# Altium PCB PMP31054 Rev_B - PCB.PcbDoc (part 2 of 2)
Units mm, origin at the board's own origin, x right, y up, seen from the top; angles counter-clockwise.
Board outline 89.28 x 61.72 mm, 4 copper layers (Top Layer, GND, Signal Layer 2, Bottom Layer), stack 2.134 mm thick; 58 components, 20 nets, 96 pads, 56 vias.
Unrouted connection lines stored in the file: 4.
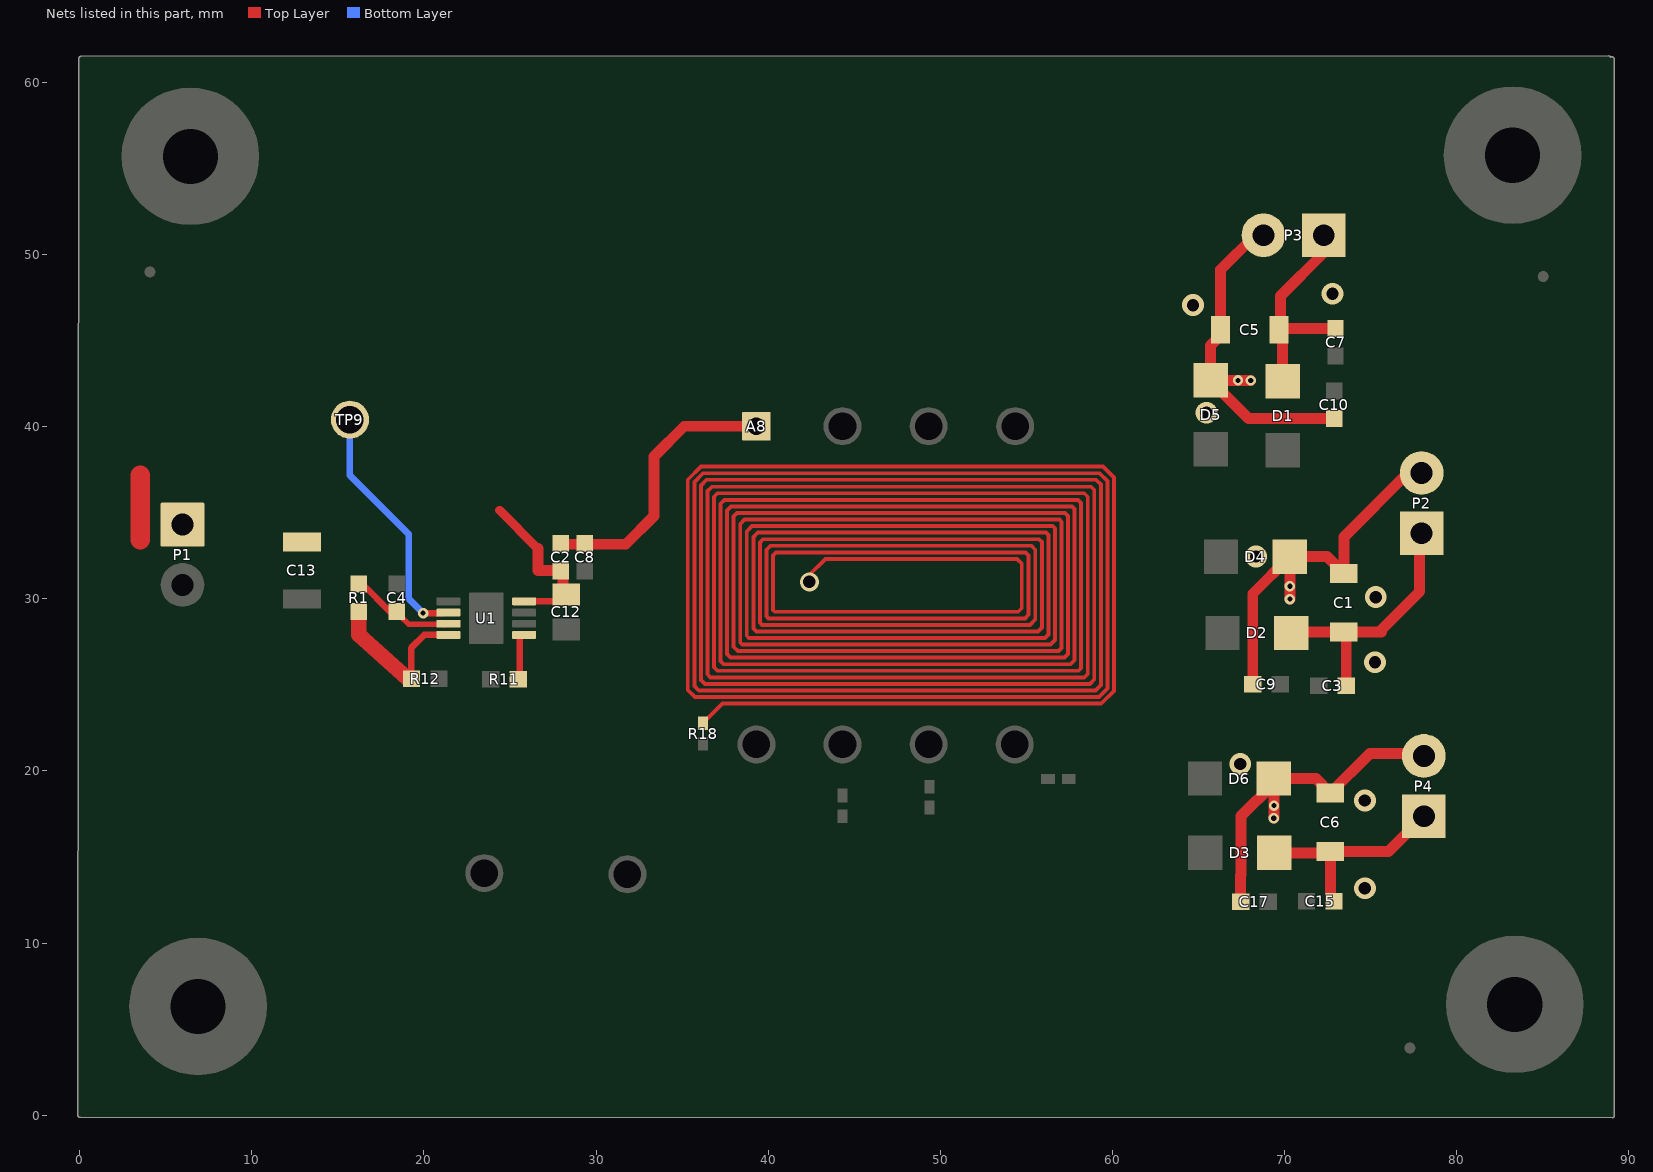
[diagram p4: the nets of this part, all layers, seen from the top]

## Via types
v1: diameter 0.6, hole 0.3, Top Layer to Bottom Layer, 29 vias
v2: diameter 1.27, hole 0.711, Top Layer to Bottom Layer, 23 vias
v3: diameter 1.1, hole 0.71, Top Layer to Bottom Layer, 4 vias

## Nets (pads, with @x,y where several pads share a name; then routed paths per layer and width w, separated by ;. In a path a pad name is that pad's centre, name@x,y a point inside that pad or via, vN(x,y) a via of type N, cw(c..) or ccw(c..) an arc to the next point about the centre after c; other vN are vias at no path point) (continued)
NetA8_1: A8.1 C2.2 C8.1 R18.1 | length 839
  Top Layer w0.225: R18.1@36.22,22.782 37.354,23.915 42.621,23.915 59.36,23.915 60.096,24.652 60.096,37.047 59.461,37.682 36.093,37.682 35.331,36.92 35.331,24.706 35.741,24.296 59.233,24.296 59.715,24.779 59.715,36.844 59.263,37.296 36.216,37.296 35.715,36.796 35.715,24.928 35.966,24.677 59.03,24.677 59.334,24.982 59.334,36.641 59.055,36.92 36.424,36.92 36.093,36.59 36.093,25.287 36.322,25.058 58.699,25.058 58.953,25.312 58.953,36.336 58.776,36.514 36.728,36.514 36.474,36.26 36.474,25.617 36.652,25.439 58.369,25.439 58.572,25.642 58.572,35.929 58.369,36.133 37.059,36.133 36.855,35.929 36.855,26.023 37.059,25.82 58.039,25.82 58.191,25.973 58.191,35.572 58.014,35.75 37.461,35.75 37.236,35.525 37.236,26.379 37.414,26.201 57.582,26.201 57.81,26.43 57.81,35.218 57.658,35.371 37.846,35.371 37.617,35.142 37.617,26.785 37.821,26.582 57.226,26.582 57.429,26.785 57.429,34.812 57.252,34.99 38.202,34.99 37.998,34.786 37.998,27.217 38.252,26.963 56.871,26.963 57.048,27.141 57.048,34.482 56.921,34.609 38.633,34.609 38.379,34.355 38.379,27.471 38.506,27.344 56.413,27.344 56.667,27.598 56.667,34.101 56.54,34.228 39.065,34.228 38.76,33.923 38.76,27.852 38.887,27.725 56.083,27.725 56.286,27.928 56.286,33.707 56.147,33.847 39.395,33.847 39.141,33.593 39.141,28.284 39.319,28.106 55.677,28.106 55.905,28.335 55.905,33.309 55.751,33.464 39.702,33.464 39.522,33.284 39.522,28.614 39.649,28.487 55.22,28.487 55.524,28.792 55.524,32.856 55.296,33.085 40.132,33.085 39.903,32.856 39.903,28.995 40.03,28.868 54.93,28.868 55.138,29.077 55.138,32.526 54.96,32.704 40.462,32.704 40.284,32.526 40.284,29.351 40.386,29.249 54.534,29.249 54.737,29.452 54.737,32.043 54.458,32.323 43.332,32.323 42.393,31.383 v3(42.393,30.988) 42.393,30.683 v3@42.266,30.556
  Top Layer w0.635: C2.2@27.953,33.172 29.35,33.172 31.725,33.172 33.376,34.823 33.376,38.278 35.128,40.03 A8.1@39.319,40.03
NetC1_1: C1.1 C3.1 D2.1 P2.1 | length 15
  Top Layer w0.635: D2.1@70.402,28.016 70.453,28.067 C1.1@73.457,28.067 ; C3.1@73.596,24.943 73.596,27.927 C1.1@73.457,28.067 ; 75.641,28.067 75.514,28.067 ; P2.1@78.054,33.579 77.864,33.389 77.864,30.417 75.514,28.067 ; C1.1@73.457,28.067 75.514,28.067
NetC1_2: C1.2 C9.2 D4.2 P2.2 | length 22.5
  Top Layer w0.635: C9.2@68.161,25.044 68.161,30.292 D4.2@70.319,32.451 ; v1(70.319,29.984) v1(70.319,30.734) D4.2@70.319,32.451 ; P2.2@77.978,37.313 77.168,37.313 73.457,33.602 C1.2@73.457,31.467 72.473,32.451 D4.2@70.319,32.451
  other v2: 75.26,26.314 75.311,30.097 68.351,32.459
NetC2_1: C2.1 C12.1 C13.1 P1.1 U1.8 | length 14.2
  Top Layer w0.381: U1.8@25.822,29.852 25.558,29.852 27.871,29.852 28.143,30.124 C12.1@28.27,30.251
  Top Layer w0.508: 24.397,35.141 26.619,32.918
  Top Layer w0.635: 26.619,32.918 26.619,31.648 28.016,31.648 28.08,31.585 28.08,30.442 C12.1@28.27,30.251
  Top Layer w1.143: 3.505,33.426 3.505,37.173
NetC4_1: C4.1 R1.2 U1.3 | length 6.3
  Top Layer w0.32: C4.1@18.237,29.045 18.593,29.045 19.126,28.512 21.382,28.512 U1.3@21.422,28.552
  Top Layer w0.381: R1.2@16.205,31.077 C4.1@18.237,29.045 ; U1.3@21.158,28.527 U1.3@21.158,28.552
NetC5_1: C5.1 C7.1 D1.1 P3.1 | length 12.9
  Top Layer w0.635: C5.1@69.774,45.695 C5.1@69.774,45.707 ; D1.1@69.901,42.64 69.901,45.439 C5.1@69.696,45.644 69.759,45.707 C5.1@69.774,45.707 ; P3.1@72.288,51.13 72.288,50.114 69.774,47.6 C5.1@69.774,45.707 ; C7.1@72.961,45.72 C7.1@72.974,45.707 C5.1@69.774,45.707
NetC5_2: C5.2 C10.2 D5.2 P3.2 | length 20.4
  Top Layer w0.635: v1(68.047,42.691) 68.04,42.697 v1(67.31,42.697) 65.716,42.697 D5.2@65.71,42.691 ; P3.2@68.783,51.13 68.304,51.13 66.296,49.122 C5.2@66.296,45.644 66.296,45.314 65.71,44.728 D5.2@65.71,42.691 ; C10.2@72.89,40.475 67.926,40.475 D5.2@65.71,42.691
  other v2: 65.481,40.818 64.694,47.066 72.796,47.727
NetC6_1: C6.1 C15.1 D3.1 P4.1 | length 12.6
  Top Layer w0.635: D3.1@69.412,15.24 72.591,15.24 C6.1@72.669,15.318 ; C15.1@72.885,12.421 72.669,12.636 C6.1@72.669,15.318 ; P4.1@78.105,17.367 76.056,15.318 C6.1@72.669,15.318
NetC6_2: C6.2 C17.2 D6.2 P4.2 | length 20
  Top Layer w0.635: C17.2@67.462,12.395 67.462,13.919 67.488,13.945 67.488,17.374 D6.2@69.386,19.272 ; v1(69.386,17.253) D6.2@69.386,19.272 ; P4.2@78.105,21.017 74.968,21.017 C6.2@72.669,18.718 71.829,19.558 D6.2@69.386,19.558 D6.2@69.386,19.272
  other v1: 69.393,17.983
  other v2: 74.676,13.183 74.676,18.288 67.437,20.396
NetR1_1: R1.1 R12.2 U1.4 | length 9
  Top Layer w0.381: R12.2@19.063,25.362 19.253,25.552 19.253,27.14 20.015,27.902 U1.4@21.158,27.902
  Top Layer w0.889: R1.1@16.205,29.045 16.205,27.902 R12.2@19.063,25.362
NetR11_2: R11.2 U1.5 | length 2.8
  Top Layer w0.381: R11.2@25.286,25.298 R11.2@25.413,25.425 ; R11.2@25.558,25.298 U1.5@25.558,27.902
NetTP9_1: TP9.1 U1.2 | length 13.2
  Top Layer w0.381: v1(19.952,29.172) 21.128,29.172 U1.2@21.158,29.202
  Bottom Layer w0.381: TP9.1@15.697,39.395 15.697,37.173 19.126,33.744 19.126,29.997 v1(19.952,29.172)
pads on no net: FID1.1 FID2.1 FID3.1 FID4.1 FID5.1 FID6.1 H1.1 H2.1 H3.1 H4.1 H5.0 H6.0 H7.0 H8.0

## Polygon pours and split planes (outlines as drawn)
GND on Top Layer "TOP_LAYER_GND_P073" (solid, remove dead copper, pour order 73): 1.981,32.492 30.429,32.492 30.429,26.417 32.842,24.409 32.842,7.963 2.997,7.963 1.981,7.963
NetC2_1 on Top Layer "TOP_LAYER_NETC2_1_P094" (solid, remove dead copper, pour order 94): 1.93,41.427 1.93,32.083 4.067,32.083 4.293,31.858 32.537,31.858 32.537,42.126 3.505,42.126
no net on Top Layer "TOP_LAYER_NONET_P067" (solid, remove dead copper, pour order 67): 24.333,35.585 24.397,35.649 26.429,35.649 27.064,35.014 27.104,32.41 27.953,31.648 27.993,30.78 26.767,30.78 26.088,31.013 24.524,31.013 24.333,31.204
NetA6_1 on Top Layer "TOP_LAYER_NETA6_1_P086" (solid, remove dead copper, pour order 86): 54.03,34.468 56.053,34.468 56.09,34.505 56.09,36.035 56.35,36.294 61.28,36.294 61.874,36.889 61.874,39.383 61.401,39.856 54.226,39.856 54.03,39.66
NetA3_1 on Top Layer "TOP_LAYER_NETA3_1_P076" (solid, remove dead copper, pour order 76): 53.162,25.565 55.194,25.565 55.44,24.359 55.639,24.041 59.385,24.041 59.576,23.787 59.576,22.459 59.116,22.136 54.496,22.136 53.204,23.427 53.204,23.914
GND on Bottom Layer "BOTTOM_LAYER_GND_P075" (solid, remove dead copper, pour order 75): 1.88,40.94 3.505,42.189 32.055,42.189 32.055,8.941 32.842,8.153 32.588,7.899 1.88,7.899
NetC6_2 on Bottom Layer "Bottom Layer-NetC6_2" (solid, pour order 202): 63.551,20.041 66.116,22.606 79.604,22.606 80.137,22.073 80.137,15.723 75.133,10.719 64.719,10.719 63.551,11.887
NetC1_2 on Bottom Layer "Bottom Layer-NetC1_2" (solid, pour order 198): 65.075,33.579 66.015,34.519 72.974,34.519 73.05,34.519 75.032,36.474 75.032,37.973 75.057,37.998 76.352,39.294 79.146,39.294 80.086,38.354 80.086,29.439 75.667,25.019 74.219,23.571 66.599,23.571 65.075,25.869
NetC5_2 on Bottom Layer "Bottom Layer-NetC5_2" (solid, pour order 194): 64.11,37.047 63.398,37.758 63.398,50.521 65.634,52.756 70.333,52.756 74.168,48.92 74.168,47.523 74.168,39.155 72.06,37.047
GND on GND "GND-No Net" (solid, pour order 170): 1.88,1.575 1.88,58.191 1.854,58.217 2.21,58.572 41.758,58.572 41.758,1.575
NetC1_2 on GND "GND-NetC1_2" (solid, pour order 184): 65.075,33.579 66.015,34.519 72.974,34.519 73.05,34.519 75.032,36.474 75.032,37.973 75.057,37.998 76.352,39.294 79.146,39.294 80.086,38.354 80.086,29.439 75.667,25.019 74.219,23.571 66.599,23.571 65.075,25.869
NetC6_2 on GND "GND-NetC6_2" (solid, pour order 186): 63.551,20.041 66.116,22.606 79.604,22.606 80.137,22.073 80.137,15.723 75.133,10.719 64.719,10.719 63.551,11.887
NetC5_2 on GND "GND-NetC5_2" (solid, pour order 174): 64.11,37.047 63.398,37.758 63.398,50.521 65.634,52.756 70.333,52.756 74.168,48.92 74.168,47.523 74.168,39.155 72.06,37.047
NetC6_2 on Signal Layer 2 "Signal Layer 2-NetC6_2" (solid, pour order 200): 63.551,20.041 66.116,22.606 79.604,22.606 80.137,22.073 80.137,15.723 75.133,10.719 64.719,10.719 63.551,11.887
NetC1_2 on Signal Layer 2 "Signal Layer 2-NetC1_2" (solid, pour order 196): 65.075,33.579 66.015,34.519 72.974,34.519 73.05,34.519 75.032,36.474 75.032,37.973 75.057,37.998 76.352,39.294 79.146,39.294 80.086,38.354 80.086,29.439 75.667,25.019 74.219,23.571 66.599,23.571 65.075,25.869
NetC5_2 on Signal Layer 2 "Signal Layer 2-NetC5_2" (solid, pour order 190): 64.11,37.047 63.398,37.758 63.398,50.521 65.634,52.756 70.333,52.756 74.168,48.92 74.168,47.523 74.168,39.155 72.06,37.047

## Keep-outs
Keep-Out Layer:
  text ".Layer_Name" at -57.531,-19.24 h1.52

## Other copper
Top Layer:
  text ".Layer_Name" at -57.531,-19.24 h1.52
GND:
  pour cut-out: 41.783,42.075 41.745,42.113 35.56,42.113 33.02,39.573 33.02,21.666 35.865,18.821 41.808,18.821
  pour cut-out: 38.361,34.341 38.361,27.457 39.086,26.732 56.979,26.732 56.979,33.438 56.076,34.341
Bottom Layer:
  text ".Layer_Name" at -57.531,-19.24 h1.52

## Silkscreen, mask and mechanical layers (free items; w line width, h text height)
Top Overlay:
  lines w0.5: 39.268,38.176 39.268,36.043 42.367,32.944 ; 42.418,31.826 42.418,32.868 ; 44.247,38.252 44.247,36.119 46.66,33.706 46.66,31.826 ; 49.276,31.725 49.276,38.278 ; 51.638,31.75 51.638,33.452 ; 51.638,33.401 51.638,33.452 ; 54.305,38.252 54.305,36.119 51.638,33.452
  text "-Vo3" at 69.571,56.337 h2.29 r90
  text "+Vo3" at 73.025,55.956 h2.29 r90
  text "FLT" at 14.351,42.647 h1.02
  text "+9 VDC" at 2.235,37.541 h2.29
  text "-Vo2" at 83.49,36.424 h2.29
  text "+Vo2" at 83.287,32.944 h2.29
  text "GND" at 3.429,26.34 h2.29
  text "-Vo1" at 83.693,19.939 h2.29
  text "+Vo1" at 83.312,16.485 h2.29
  text "SW-Node" at 29.464,8.852 h1.02
  text "GND" at 22.2,8.814 h1.02
  text "PMP31054 Rev A" at 43.383,4.089 h2.29
  text ".Layer_Name" at -57.531,-19.24 h1.52
Bottom Overlay:
  text ".Layer_Name" at -57.531,-19.24 h1.52
Top Paste:
  text ".Layer_Name" at -57.531,-19.24 h1.52
Bottom Paste:
  text ".Layer_Name" at -57.531,-19.24 h1.52
Top Solder:
  text ".Layer_Name" at -57.531,-19.24 h1.52
  text ".Layer_Name" at -57.531,-19.24 h1.52
Bottom Solder:
  text ".Layer_Name" at -57.531,-19.24 h1.52
Drill Guide:
  text ".Layer_Name" at -57.531,-19.24 h1.52
M1 Board Outline:
  lines w0.254: 88.837,61.43 0.075,61.396 0.011,-0.004 89.04,-0.038 89.04,61.366
  text ".Layer_Name" at -57.531,-19.24 h1.52
M2 Board Dimensions:
  rectangle: -72.187,-4.42 -69.012,-1.245
  rectangle: -69.012,-7.595 -59.487,-4.42
  lines w0.178: -72.187,-4.42 -46.787,-4.42 ; -69.012,-7.595 -69.012,-1.245 ; -65.837,-7.595 -65.837,-1.245 ; -59.487,-7.595 -59.487,-1.245 ; -53.137,-7.595 -53.137,-1.245 ; -72.187,-7.595 -46.787,-7.595 -46.787,-1.245 -72.187,-1.245 -72.187,-7.595
  lines w0.254: -3.861,1.268 -3.353,-0.256 ; -3.861,59.688 -3.353,61.212 ; -3.607,-0.256 -3.099,-0.256 ; -3.607,61.212 -3.099,61.212 ; -3.353,22.581 -3.353,-0.256 ; -3.353,38.375 -3.353,61.212 ; -2.845,1.268 -3.353,-0.256 ; -2.845,59.688 -3.353,61.212 ; -0.001,64.567 0.001,64.059 ; 1.522,64.828 0,64.313 ; 1.526,63.812 0,64.313 ; 34.979,64.482 0,64.313 ; 54.074,64.575 89.052,64.745 ; 87.526,65.245 89.052,64.745 ; 87.531,64.229 89.052,64.745 ; 89.051,64.999 89.054,64.491
  text "89.05345 (mm)" at 35.237,63.569 h1.52 r0.28
  text "61.468 (mm)" at -2.438,22.835 h1.52 r90
  text ".Layer_Name" at -57.531,-19.24 h1.52
M3 3D STEP Top:
  text ".Layer_Name" at -57.531,-19.24 h1.52
M4 3D STEP Bottom:
  text ".Layer_Name" at -57.531,-19.24 h1.52
M5 Assembly Top:
  lines w0.254: -79.604,-21.061 88.036,-21.061 ; -79.604,-15.896 88.087,-15.896 ; -79.604,-10.731 -79.604,-26.226 22.123,-26.226 88.087,-26.226 88.087,-10.732 -79.591,-10.732 -79.591,-26.226 -39.573,-26.226 ; -16.993,-26.226 -16.993,-10.732 ; 2.222,22.949 2.362,23.089 ; 14.173,22.949 14.3,23.076 ; 14.236,34.95 14.3,34.887 ; 15.189,-15.896 15.189,-10.732 ; 36.525,-15.896 36.525,-10.732 ; 52.324,-26.391 52.324,-21.239
  text "COMPONENTS MARKED 'DNP' SHOULD NOT BE POPULATED." at -42.888,-5.524 h1.52
  text "ASSEMBLY VARIANT:" at -42.901,-8.458 h1.52
  text ".VariantName" at -16.586,-8.458 h1.52
  text "PCB VIEWED FROM TOP SIDE" at -77.991,-14.089 h1.52
  text "BOARD #:" at -15.088,-14.089 h1.52
  text ".PRJ_Number" at -1.232,-14.089 h1.52
  text "REV:" at 20.218,-14.089 h1.52
  text ".PCB_Rev" at 27.622,-14.089 h1.52
  text "SVN REV:" at 41.504,-14.089 h1.52
  text ".VersionControl_RevNumber" at 54.356,-14.089 h1.52
  text "TID #:" at -15.088,-19.253 h1.52
  text ".TID" at -1.232,-19.253 h1.52
  text "PLOT NAME =" at -77.991,-24.469 h1.52
  text ".plot_File_Name" at -57.531,-24.469 h1.52
  text "GENERATED    :" at -15.037,-24.469 h1.52
  text ".Print_Date" at 7.048,-24.469 h1.52
  text ".Print_Time" at 25.565,-24.469 h1.52
  text "TEXAS INSTRUMENTS" at 57.683,-24.469 h1.52
M6 Assembly Bottom:
  lines w0.254: -79.616,-15.909 88.075,-15.909 ; -79.566,-21.074 88.075,-21.074 ; -43.853,-26.403 -43.853,-21.251 ; -28.054,-15.909 -28.054,-10.744 ; -6.718,-15.909 -6.718,-10.744 ; 25.463,-26.238 25.463,-10.744 ; 48.044,-26.238 88.062,-26.238 88.062,-10.744 -79.616,-10.744 -79.616,-26.238 -13.652,-26.238 88.075,-26.238 88.075,-10.744
  text "COMPONENTS MARKED 'DNP' SHOULD NOT BE POPULATED." at 82.804,-5.512 h1.52
  text ".VariantName" at 56.286,-8.458 h1.52
  text "ASSEMBLY VARIANT:" at 82.677,-8.458 h1.52
  text ".VersionControl_RevNumber" at -45.885,-14.101 h1.52
  text "SVN REV:" at -33.033,-14.101 h1.52
  text ".PCB_Rev" at -19.152,-14.101 h1.52
  text "REV:" at -11.747,-14.101 h1.52
  text ".PRJ_Number" at 9.703,-14.101 h1.52
  text "BOARD #:" at 23.558,-14.101 h1.52
  text "PCB VIEWED FROM BOTTOM SIDE" at 86.462,-14.101 h1.52
  text ".TID" at 9.703,-19.266 h1.52
  text "TID #:" at 23.558,-19.266 h1.52
  text "TEXAS INSTRUMENTS" at -49.212,-24.481 h1.52
  text ".Print_Time" at -17.094,-24.481 h1.52
  text ".Print_Date" at 1.422,-24.481 h1.52
  text "GENERATED    :" at 23.508,-24.481 h1.52
  text ".plot_File_Name" at 66.002,-24.481 h1.52
  text "PLOT NAME =" at 86.462,-24.481 h1.52
M9 Title Sheet:
  drawing of 57 lines, arcs and shapes, not listed
  text "1" at -53.395,206.692 h1.78
  text "2" at 9.995,206.692 h1.78
  text "3" at 73.224,206.692 h1.78
  text "4" at 136.894,206.692 h1.78
  text "5" at 200.368,206.692 h1.78
  text "6" at 263.995,206.692 h1.78
  text "A" at -82.766,177.66 h1.78
  text "A" at 293.154,177.66 h1.78
  text "B" at -82.766,117.208 h1.78
  text "B" at 293.154,117.208 h1.78
  text "C" at -82.766,56.883 h1.78
  text "C" at 293.154,56.883 h1.78
  text "PROJECT TITLE:" at 215.938,9.614 h1.14
  text ".PRJ_Title" at 217.208,6.227 h1.78
  text "DESIGNED FOR:" at 215.938,1.968 h1.14
  text ".PRJ_Customer" at 217.208,-1.587 h1.78
  text "D" at -82.766,-3.315 h1.78
  text "D" at 293.154,-3.315 h1.78
  text "FILE NAME:" at 215.938,-5.651 h1.14
  text ".PCB_File_Name_No_Path" at 217.208,-8.7 h1.78
  text "Texas Instruments (TI) and/or its licensors do not warrant the accuracy or completeness of this specification" at 89.713,-12.81 h1.14
  text "ENGINEER:" at 215.938,-13.018 h1.14
  text "LAYOUT BY:" at 254.165,-13.018 h1.14
  text "or any information contained therein. TI and/or its licensors do not warrant that this design will meet" at 88.57,-15.672 h1.14
  text ".PRJ_Engineer" at 217.208,-16.954 h1.78
  text ".PCB_Layout" at 255.448,-16.954 h1.78
  text "the specifications, will be suitable for your application or fit for any particular purpose, or will operate in" at 88.57,-18.534 h1.14
  text ".Layer_Name" at -57.531,-19.24 h1.52
  text "ALTIUM DESIGNER VERSION:" at 254.165,-20.892 h1.14
  text "an implementation. TI and/or its licensors do not warrant that the design is production worthy. You should" at 88.57,-21.395 h1.14
  text "completely validate and test your design implementation to confirm the system functionality for your application." at 89.713,-24.257 h1.14
  text ".print_Scale" at 217.208,-24.278 h1.78
  text ".Application_BuildNumber" at 255.448,-24.278 h1.78
  text "1" at -53.395,-29.527 h1.78
  text "2" at 9.995,-29.527 h1.78
  text "3" at 73.224,-29.527 h1.78
  text "4" at 136.894,-29.527 h1.78
  text "5" at 200.368,-29.527 h1.78
  text "6" at 263.995,-29.527 h1.78
M10 Fab Notes:
  drawing of 189 lines, arcs and shapes, not listed
  text "DESIGN INFORMATION" at 242.316,164.012 h1.52
  text "MIN. TRACK WIDTH:" at 225.945,160.656 h1.52
  text "8" at 253.789,160.656 h1.52
  text "MIL" at 257.72,160.656 h1.52
  text "MIN. CLEARANCE:" at 225.945,157.503 h1.52
  text "0.2" at 252.265,157.504 h1.52
  text "mm" at 257.72,157.503 h1.52
  text "MIN. VIA PAD SIZE:" at 225.945,154.351 h1.52
  text "24" at 253.027,154.351 h1.52
  text "MIL" at 257.72,154.351 h1.52
  text "0.05mm (2MIL)" at 243.598,151.051 h1.52
  text "MINIMUM ANNULAR RING" at 217.582,150.842 h1.52
  text "EXTERNAL" at 261.581,150.842 h1.52
  text "PER" at 222.662,148.045 h1.52
  text "IPC-D-275 CLASS 2 LEVEL C" at 228.25,148.045 h1.52
  text "MIL, HOLES" at 266.051,145.493 h1.52
  text "+/-" at 256.083,145.275 h1.52
  text "+/-" at 277.774,145.275 h1.52
  text "REGISTRATION TOLERANCES:" at 217.582,145.248 h1.52
  text "METAL" at 248.056,145.248 h1.52
  text "5" at 262.692,145.248 h1.52
  text "3" at 283.85,145.248 h1.52
  text "MIL" at 286.803,145.248 h1.52
  text "HOLE SIZE TOLERANCE (UNLESS OTHERWISE SPECIFIED):" at 217.582,142.751 h1.52
  text "+/-" at 277.774,142.678 h1.52
  text "3" at 283.85,142.651 h1.52
  text "MIL" at 286.803,142.651 h1.52
  text "MATERIAL:" at 215.683,139.154 h1.52
  text "FR-4 High Tg" at 240.739,135.89 h1.52
  text "X" at 237.07,135.687 h1.52
  text "FR-408" at 226.377,135.572 h1.52
  text "OTHER" at 264.172,135.572 h1.52
  text "62 MIL (1.6mm) +/-10%" at 234.507,131.939 h1.52
  text "X" at 231.457,131.877 h1.52
  text "THICKNESS:" at 217.582,131.73 h1.52
  text "OTHER" at 267.143,131.73 h1.52
  text "TOLERANCE:" at 217.582,128.217 h1.52
  text "X" at 239.127,128.217 h1.52
  text "ANSI IPC-6012 TYPE 3 CLASS 2" at 243.649,128.217 h1.52
  text "OTHER +/-" at 243.648,124.555 h1.52
  text "BOW & TWIST:" at 217.582,120.867 h1.52
  text "X" at 239.127,120.867 h1.52
  text "ANSI IPC-6012 TYPE 3 CLASS 2" at 243.649,120.867 h1.52
  text "OTHER +/-" at 243.648,117.141 h1.52
  text "DRILLING:" at 215.683,113.823 h1.52
  text "NC_DRILL FILES" at 260.412,111.151 h1.52
  text "REFERENCE:" at 217.582,111.051 h1.52
  text "X" at 234.276,111.049 h1.52
  text "AS SHOWN" at 238.797,111.051 h1.52
  text "X" at 257.161,111.051 h1.52
  text "OTHER" at 267.982,107.438 h1.52
  text "PTH COPPER THICKNESS:" at 217.574,107.349 h1.52
  text "X" at 246.511,107.349 h1.52
  text "20-30 um" at 249.762,107.349 h1.52
  text "BOARD FINISH:" at 215.683,103.6 h1.52
  text "SILKSCREEN:" at 219.626,100.802 h1.52
  text "X" at 243.953,100.802 h1.52
  text "TOP" at 246.925,100.802 h1.52
  text "X" at 256.907,100.802 h1.52
  text "BOTTOM" at 259.904,100.802 h1.52
  text "SILKSCREEN COLOR:" at 219.626,96.861 h1.52
  text "X" at 243.928,96.861 h1.52
  text "WHITE" at 246.925,96.861 h1.52
  text "OTHER" at 259.904,96.861 h1.52
  text "X" at 247.255,93.217 h1.52
  text "GREEN" at 250.252,93.217 h1.52
  text "OTHER" at 265.95,93.217 h1.52
  text "SOLDER RESIST COLOR:" at 219.626,93.043 h1.52
  text "X" at 247.255,89.299 h1.52
  text "MATTE" at 250.252,89.299 h1.52
  text "SEMI-GLOSS" at 265.938,89.283 h1.52
  text "IMMERSION GOLD (ENIG)" at 242.632,84.911 h1.52
  text "ENEPIG" at 276.606,84.727 h1.52
  text "SURFACE FINISH:" at 215.683,84.702 h1.52
  text "X" at 238.111,84.702 h1.52
  text "IMM. TIN/SILVER OR EQUIV" at 224.053,81.214 h1.52
  text "OTHER" at 260.412,81.114 h1.52
  text "ARRAY/PANEL:" at 215.683,77.167 h1.52
  text "CUT AND TRIM PER M1 BOARD OUTLINE" at 242.632,76.959 h1.52
  text "N.C. ROUTE" at 242.632,73.505 h1.52
  text "X" at 260.108,73.505 h1.52
  text "V. SCORE" at 264.629,73.505 h1.52
  text "CERTIFICATION:" at 215.683,70.225 h1.52
  text "MATERIALS AND WORKMANSHIP FOR ALL PCBS" at 234.098,70.225 h1.52
  text "TO MEET OR EXCEED THE REQUIREMENTS OF:" at 234.098,67.836 h1.52
  text "X" at 224.891,64.569 h1.52
  text "ANSI IPC-A-600F CLASS ->" at 228.142,64.569 h1.52
  text "X" at 270.001,64.569 h1.52
  text "2" at 272.795,64.569 h1.52
  text "1" at 264.794,64.531 h1.52
  text "3" at 281.787,64.531 h1.52
  text "X" at 245.516,60.818 h1.52
  text "RoHS" at 248.767,60.818 h1.52
  text "OTHER" at 265.134,60.818 h1.52
  text "PER ORDER" at 275.22,60.818 h1.52
  text "ALL BOARDS MUST MEET OR EXCEED UL94-V0 REQUIREMENTS." at 216.383,56.91 h1.52
  text "PCB MUST BEAR THE UL94V-0 UL REGISTERED MATERIAL ID NUMBER" at 216.383,53.962 h1.52
  text "ADDITIONAL REQUIREMENTS:" at 215.683,49.659 h1.52
  text "MICROSECTION:" at 217.582,46.938 h1.52
  text "YES" at 240.588,46.938 h1.52
  text "REQUIRED" at 262.47,43.272 h1.52
  text "BARE BOARD ELEC. TEST:" at 217.582,43.199 h1.52
  text "NONE" at 250.748,43.199 h1.52
  text "X" at 259.473,43.199 h1.52
  text "PER ORDER" at 277.507,43.199 h1.52
  text "XX MIL VIAS REQUIRE NON-CONDUCTIVE FILL AND PLANARIZE" at 221.853,37.994 h1.5
  text "XX MIL VIAS REQUIRE CONDUCTIVE FILL AND PLANARIZE" at 222.056,35.353 h1.52
  text "OUTER XX MIL TRACES REQUIRE 50 OHM SINGLE-ENDED IMPEDANCE" at 222.031,31.203 h1.47
  text "LAYER 2 & 3 (INNER LAYERS) XX MIL WIDE, XX MIL SPACE / TRACES REQUIRE 100 OHM DIFFERENTIAL IMPEDANCE" at 221.828,25.216 h1.52
  text ".Layer_Name" at -57.531,-19.24 h1.52
M11 Gerber Information:
  lines w0.254: -79.604,-21.061 88.036,-21.061 ; -79.604,-15.896 88.087,-15.896 ; -79.604,-10.731 -79.604,-26.226 22.123,-26.226 88.087,-26.226 88.087,-10.732 -79.591,-10.732 -79.591,-26.226 -39.573,-26.226 ; -16.993,-26.226 -16.993,-10.732 ; 15.189,-15.896 15.189,-10.732 ; 36.525,-15.896 36.525,-10.732 ; 52.324,-26.391 52.324,-21.239
  text "ALL ARTWORK VIEWED FROM TOP SIDE" at -77.991,-14.089 h1.52
  text "BOARD #:" at -15.088,-14.089 h1.52
  text ".PRJ_Number" at -1.232,-14.089 h1.52
  text "REV:" at 20.218,-14.089 h1.52
  text ".PCB_Rev" at 27.622,-14.089 h1.52
  text "SVN REV:" at 41.504,-14.089 h1.52
  text ".VersionControl_RevNumber" at 54.356,-14.089 h1.52
  text "LAYER NAME =" at -77.991,-19.24 h1.52
  text "TID #:" at -15.088,-19.253 h1.52
  text ".TID" at -1.232,-19.253 h1.52
  text "PLOT NAME =" at -77.991,-24.469 h1.52
  text ".plot_File_Name" at -57.531,-24.469 h1.52
  text "GENERATED    :" at -15.037,-24.469 h1.52
  text ".Print_Date" at 7.048,-24.469 h1.52
  text ".Print_Time" at 25.565,-24.469 h1.52
  text "TEXAS INSTRUMENTS" at 57.683,-24.469 h1.52
M12 Stackup:
  drawing of 295 lines, arcs and shapes, not listed
  text "Layer" at 177.18,185.928 h1.52
  text "Name" at 187.591,185.928 h1.52
  text "Material" at 211.461,185.928 h1.52
  text "Thickness" at 233.299,185.928 h1.52
  text "Constant" at 249.805,185.928 h1.52
  text "Board Layer Stack" at 264.279,185.928 h1.52
  text "Top Overlay" at 187.591,182.88 h1.52
  text "Top Solder" at 187.591,179.832 h1.52
  text "Solder Resist" at 211.461,179.832 h1.52
  text "0,40mil" at 233.299,179.832 h1.52
  text "3.5" at 249.805,179.832 h1.52
  text "1" at 177.18,176.784 h1.52
  text "Top Layer" at 187.591,176.784 h1.52
  text "1,40mil" at 233.299,176.784 h1.52
  text "Dielectric1" at 187.591,173.736 h1.52
  text "FR-4 High Tg" at 211.461,173.736 h1.52
  text "58,40mil" at 233.299,173.736 h1.52
  text "4.8" at 249.805,173.736 h1.52
  text "2" at 177.18,170.688 h1.52
  text "GND" at 187.591,170.688 h1.52
  text "1,42mil" at 233.299,170.688 h1.52
  text "Dielectric 2" at 187.591,167.64 h1.52
  text "10,00mil" at 233.299,167.64 h1.52
  text "4.2" at 249.805,167.64 h1.52
  text "3" at 177.18,164.592 h1.52
  text "Signal Layer 2" at 187.591,164.592 h1.52
  text "1,42mil" at 233.299,164.592 h1.52
  text "Dielectric 3" at 187.591,161.544 h1.52
  text "10,00mil" at 233.299,161.544 h1.52
  text "4.2" at 249.805,161.544 h1.52
  text "4" at 177.18,158.496 h1.52
  text "Bottom Layer" at 187.591,158.496 h1.52
  text "1,40mil" at 233.299,158.496 h1.52
  text "Bottom Solder" at 187.591,155.448 h1.52
  text "Solder Resist" at 211.461,155.448 h1.52
  text "0,40mil" at 233.299,155.448 h1.52
  text "3.5" at 249.805,155.448 h1.52
  text "Bottom Overlay" at 187.591,152.4 h1.52
  text ".Layer_Name" at -57.531,-19.24 h1.52
M13 Component Bodies Top:
  text ".Layer_Name" at -57.531,-19.24 h1.52
M14 Component Bodies Bottom:
  text ".Layer_Name" at -57.531,-19.24 h1.52
M15 Courtyards Top:
  text ".Layer_Name" at -57.531,-19.24 h1.52
M16 Courtyards Bottom:
  text ".Layer_Name" at -57.531,-19.24 h1.52
Drill Drawing:
  circle w0.254: c105.937,101.636 r0.702
  lines w0.254: 105.235,91.812 105.586,91.812 105.937,91.461 106.288,91.812 106.639,91.812 106.288,92.163 106.639,92.514 106.288,92.514 105.937,92.865 105.586,92.514 105.235,92.514 105.586,92.163 105.235,91.812 ; 105.235,94.619 106.639,94.619 106.639,96.023 105.235,96.023 105.235,94.619 ; 105.235,98.128 105.586,98.128 105.937,97.777 106.288,98.128 106.639,98.128 106.288,98.479 106.639,98.829 106.288,98.829 105.937,99.18 105.586,98.829 105.235,98.829 105.586,98.479 105.235,98.128 ; 105.235,104.092 105.937,104.443 106.639,104.092 106.288,104.794 106.639,105.496 105.937,105.145 105.235,105.496 105.586,104.794 105.235,104.092 ; 105.235,108.653 106.639,108.653 105.937,107.25 105.235,108.653 ; 105.235,110.759 105.586,110.759 105.586,110.408 106.288,110.408 106.288,110.759 106.639,110.759 106.639,111.46 106.288,111.46 106.288,111.811 105.586,111.811 105.586,111.46 105.235,111.46 105.235,110.759 ; 105.516,98.268 105.727,98.268 105.937,98.058 106.148,98.268 106.358,98.268 106.148,98.479 106.358,98.689 106.148,98.689 105.937,98.9 105.727,98.689 105.516,98.689 105.727,98.479 105.516,98.268 ; 105.516,104.373 105.937,104.584 106.358,104.373 106.148,104.794 106.358,105.215 105.937,105.005 105.516,105.215 105.727,104.794 105.516,104.373 ; 105.516,108.373 106.358,108.373 105.937,107.531 105.516,108.373
  lines w0.305: 103.963,90.514 186.043,90.514 ; 103.963,112.618 186.043,112.618 ; 112.545,87.356 112.545,115.776 ; 120.978,87.356 120.978,115.776 ; 137.146,87.356 137.146,115.776 ; 143.728,87.356 143.728,115.776 ; 153.257,87.356 153.257,115.776 ; 171.655,87.356 171.655,115.776 ; 103.963,87.356 186.043,87.356 186.043,115.776 103.963,115.776 103.963,87.356
  text "Symbol" at 105.858,113.565 h1.83
  text "Quantity" at 113.492,113.565 h1.83
  text "Finished Hole Size" at 121.925,113.565 h1.83
  text "Plated" at 138.094,113.565 h1.83
  text "Hole Type" at 144.676,113.565 h1.83
  text "Drill Layer Pair" at 154.205,113.565 h1.83
  text "Hole Tolerance" at 172.603,113.565 h1.83
  text "29" at 113.492,110.408 h1.52
  text "11,81mil (0,300mm)" at 121.925,110.408 h1.52
  text "PTH" at 138.094,110.408 h1.52
  text "Round" at 144.676,110.408 h1.52
  text "Top Layer - Bottom Layer" at 154.205,110.408 h1.52
  text "4" at 113.492,107.25 h1.52
  text "27,95mil (0,710mm)" at 121.925,107.25 h1.52
  text "PTH" at 138.094,107.25 h1.52
  text "Round" at 144.676,107.25 h1.52
  text "Top Layer - Bottom Layer" at 154.205,107.25 h1.52
  text "23" at 113.492,104.092 h1.52
  text "28,00mil (0,711mm)" at 121.925,104.092 h1.52
  text "PTH" at 138.094,104.092 h1.52
  text "Round" at 144.676,104.092 h1.52
  text "Top Layer - Bottom Layer" at 154.205,104.092 h1.52
  text "1" at 113.492,100.935 h1.52
  text "40,00mil (1,016mm)" at 121.925,100.935 h1.52
  text "PTH" at 138.094,100.935 h1.52
  text "Round" at 144.676,100.935 h1.52
  text "Top Layer - Bottom Layer" at 154.205,100.935 h1.52
  text "8" at 113.492,97.777 h1.52
  text "50,00mil (1,270mm)" at 121.925,97.777 h1.52
  text "PTH" at 138.094,97.777 h1.52
  text "Round" at 144.676,97.777 h1.52
  text "Top Layer - Bottom Layer" at 154.205,97.777 h1.52
  text "10" at 113.492,94.619 h1.52
  text "63,00mil (1,600mm)" at 121.925,94.619 h1.52
  text "PTH" at 138.094,94.619 h1.52
  text "Round" at 144.676,94.619 h1.52
  text "Top Layer - Bottom Layer" at 154.205,94.619 h1.52
  text "4" at 113.492,91.461 h1.52
  text "125,98mil (3,200mm)" at 121.925,91.461 h1.52
  text "PTH" at 138.094,91.461 h1.52
  text "Round" at 144.676,91.461 h1.52
  text "Top Layer - Bottom Layer" at 154.205,91.461 h1.52
  text "79 Total" at 113.492,88.304 h1.52
  text ".Layer_Name" at -57.531,-19.24 h1.52
M17 Embedded Cavity:
  text ".Layer_Name" at -57.531,-19.24 h1.52
M18 Embedded Assembly:
  text ".Layer_Name" at -57.531,-19.24 h1.52
M19 Embedded Keepout:
  text ".Layer_Name" at -57.531,-19.24 h1.52

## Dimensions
-72.187,-7.595 to -46.787,-7.595 on M2 Board Dimensions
